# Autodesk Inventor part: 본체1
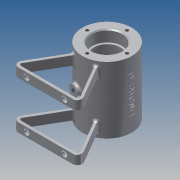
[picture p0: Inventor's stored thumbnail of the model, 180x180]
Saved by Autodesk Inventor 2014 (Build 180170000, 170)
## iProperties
Created: 2016-03
Part Number: 본체1
Material: 알루미늄 6061
Document SubType Name: Modeling
Designer: 406-003
Density: 2.71 g/cm^3
Appearance: 알루미늄 - 평지
Mass: 210.237 g
Surface Area: 325.992 cm^2
Volume: 77.5781 cm^3
Author: 406-003
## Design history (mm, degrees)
sketch "스케치1"
  geometry: C1 r 26 at (0, 0); 1 further point
  constraints: 1 centre point, 1 coincident
  dimensions: "d0" = 52 diameter of C1
extrude "돌출1" new body sketch "스케치1" distance "d1" = 70; taper "d2" = 0 deg
sketch "스케치2"
  geometry: C1 r 26 at (0, 0) reference; 1 further point
  constraints: 1 coincident
hole "구멍1" sketch "스케치2" at (0, 0) diameter "d4" = 28; stored, may be unused: countersink angle "d8" = 90 deg, drill point angle "d10" = 0 deg; dims "d5" = 6, "d6" = 32, "d7" = 12, "d9" = 14
fillet "모깎기1" dims "d11" = 0.3
node "작업 평면1"
sketch "스케치4"
  geometry: L1 (14, -14)-(-14, -14) reference; L2 (14, -56)-(-14, -56) reference; L3 (0, -14)-(0, -56); L4 (21, -14)-(21, -56); L5 (0, -14)-(21, -14); L6 (0, -56)-(21, -56); 1 further point
  constraints: 8 end point, 2 midpoint, 1 parallel, 1 perpendicular, 1 point on line
  dimensions: "d13" = 42 diameter of L4 L3
revolve "회전1" sketch "스케치4" stored, may be unused: angle "d14" = 90 deg
fillet "모깎기2" dims "d15" = 3
fillet "모깎기3" dims "d16" = 0.3
chamfer "모따기1" distance "d17" = 1; stored, may be unused: second distance "d18" = 2, angle "d19" = 45 deg
sketch "스케치5"
  geometry: L1 (0, 21)-(0, -21); C1 r 17 at (0, 0) reference; A1 r 21 centre (0, 0) between (0, 21) and (0, -21)
  constraints: 2 end point, 2 point on circle, 1 centre point, 1 coincident, 1 vertical
  dimensions: "d20" = 42 diameter of A1; "d21" = 0 distance from line of C1.centre L1
hole "구멍2" sketch "스케치5" at (0, 21) diameter "d22" = 3.242; stored, may be unused: countersink angle "d26" = 90 deg, drill point angle "d28" = 118 deg; dims "d23" = 8, "d24" = 32, "d25" = 12, "d27" = 10
node "작업 평면3"
  node "작업 평면2"
sketch "스케치6"
  geometry: L1 (0, 0)-(0, -35); C1 r 5 at (0, -35)
  constraints: 2 end point, 1 centre point, 1 coincident, 1 vertical
  dimensions: "d33" = 35 distance of L1.start L1.end; "d34" = 10 diameter of C1
extrude "돌출2" join sketch "스케치6" stored distance "d35" = 42; taper "d36" = 0 deg
fillet "모깎기4" dims "d37" = 2
sketch "스케치7"
  geometry: C1 r 5 at (0, 0) reference; 2 further points
  constraints: 1 coincident
hole "구멍3" sketch "스케치7" at (0, 0) diameter "d38" = 5.188; stored, may be unused: countersink angle "d42" = 90 deg, drill point angle "d44" = 118 deg; dims "d39" = 19, "d40" = 32, "d41" = 12, "d43" = 20
sketch "스케치8"
  geometry: L1 (0, 0)-(0, -26); L2 (0, 0)-(-7.506, -28.012); C1 r 1.621 at (21, 0) reference; C2 r 1.621 at (0, -21) reference; C3 r 1.621 at (-21, 0) reference; C4 r 1.621 at (0, 21) reference; C5 r 17 at (0, 0) reference; 1 further point
  constraints: 4 end point, 1 vertical, 1 vertical alignment, 1 other
  dimensions: "d46" = 15 deg angle of L2 L1; "d47" = 29 distance of L1.start L2.end
node "작업 평면5"
sketch "스케치9"
  geometry: L1 (0, 0)-(0, -35); C1 r 6 at (0, -35)
  constraints: 2 end point, 1 centre point, 1 coincident, 1 vertical
  dimensions: "d48" = 35 distance of L1.start L1.end; "d49" = 12 diameter of C1
extrude "돌출3" join sketch "스케치9" stored distance "d50" = 42; taper "d51" = 0 deg
sketch "스케치10"
  geometry: C1 r 6 at (0, 0) reference; 2 further points
  constraints: 1 coincident
hole "구멍4" sketch "스케치10" at (0, 0) diameter "d52" = 5.188; stored, may be unused: countersink angle "d56" = 90 deg, drill point angle "d58" = 118 deg; dims "d53" = 19, "d54" = 32, "d55" = 12, "d57" = 20
fillet "모깎기5" dims "d59" = 2
node "작업 평면6"
sketch "스케치11"
  geometry: L1 (0, 0)-(0, -65); L2 (0, -65)-(28.868, -65); L3 (0, -65)-(-28.868, -65); L4 (28.868, -62)-(0, -62); L5 (-28.868, -62)-(0, -62); L6 (-9.499, -22.57)-(-30.598, -58.998); L7 (-11.244, -20)-(-33.182, -57.474); L8 (9.499, -22.57)-(30.598, -58.998); L9 (11.244, -20)-(33.182, -57.474); C1 r 21 at (0, 0) reference; A1 r 5 centre (-28.868, -60) between (-33.182, -57.474) and (-28.868, -65); A2 r 5 centre (28.868, -60) between (28.868, -65) and (33.182, -57.474); A3 r 2 centre (28.868, -60) between (28.868, -62) and (30.598, -58.998); A4 r 2 centre (-28.868, -60) between (-30.598, -58.998) and (-28.868, -62); A5 r 22.944 centre (0, 0) between (-11.244, -20) and (11.244, -20); A6 r 3.457 centre (-28.868, -60) between (-32.011, -61.437) and (-31.687, -62); A7 r 24.487 centre (0, 0) between (-9.499, -22.57) and (9.499, -22.57)
  constraints: 18 end point, 14 point on circle, 7 centre point, 6 tangent, 2 point on line, 1 coincident, 1 collinear, 1 equal radius, 1 perpendicular, 1 vertical, 2 other
  dimensions: "d61" = 65 distance of L1.start L1.end; "d64" = 5 radius of A1; "d65" = 3 distance between parallel lines of L3 L5; "d66" = 3 distance between parallel lines of L2 L4; "d67" = 45 distance from line of L2 L9.start; "d68" = 45 distance from line of L3 L7.start; "d71" = 0.266242 deg angle of L8 L9; "d72" = 59.6539 deg angle of L9 L4; "d73" = 60.4259 deg angle of L6 L9; "d74" = 60.6921 deg angle of L9 L7; "d75" = 30.92281 distance from line of L4.end L9; "d76" = 30.92281 distance from line of L5.end L9; "d79" = 24.4874 radius of A7; "d80" = 22.94403 radius of A5; "d81" = 3.45663 radius of A6
extrude "돌출4" join sketch "스케치11" distance "d82" = 10; taper "d83" = 0 deg
sketch "스케치12"
  geometry: L1 (-33.182, -57.474)-(-12.788, -22.638) reference; L2 (12.788, -22.638)-(33.182, -57.474) reference; L3 (-9.499, -22.57)-(-30.598, -58.998) reference; L4 (9.499, -22.57)-(30.598, -58.998) reference; L5 (28.868, -62)-(0, -62) reference; L6 (-28.868, -62)-(0, -62) reference; A1 r 26 centre (0, 0) between (-12.788, -22.638) and (12.788, -22.638) reference; A2 r 24.487 centre (0, 0) between (-9.499, -22.57) and (9.499, -22.57) reference; A3 r 2 centre (28.868, -60) between (28.868, -62) and (30.598, -58.998) reference; A4 r 2 centre (-28.868, -60) between (-30.598, -58.998) and (-28.868, -62) reference; A5 r 26 centre (0, 0) between (-10.263, -23.889) and (10.263, -23.889); A6 r 26 centre (0, 0) between (12.788, -22.638) and (-12.788, -22.638)
  constraints: 4 point on circle, 2 centre point, 2 end point, 2 point on line, 1 coincident
  dimensions: "d84" = 26 radius of A5
extrude "돌출5" cut sketch "스케치12" distance "d85" = 10; taper "d86" = 0 deg
sketch "스케치13"
  geometry: L1 (0, 0)-(57.735, 0) reference; L2 (57.735, -10)-(0, -10) reference; L3 (28.868, 0)-(28.868, -10); L4 (8.868, 0)-(8.868, -10); L5 (48.868, 0)-(48.868, -10); C1 r 3 at (8.868, -5); C2 r 3 at (48.868, -5); 1 further point
  constraints: 6 end point, 4 midpoint, 2 centre point, 2 parallel
  dimensions: "d87" = 40 distance between parallel lines of L5 L4; "d88" = 20 distance between parallel lines of L3 L4; "d89" = 5 distance from line of L1 C1.centre; "d90" = 6 diameter of C1; "d91" = 6 diameter of C2; "d92" = 5 distance from line of C2.centre L1
extrude "돌출6" cut sketch "스케치13" distance "d93" = 10; taper "d94" = 0 deg
fillet "모깎기6" dims "d95" = 0.5
fillet "모깎기7" dims "d96" = 0.5
fillet "모깎기8" dims "d97" = 3
node "작업 평면8"
node "작업 평면9"
sketch "스케치16"
  geometry: L1 (0, 0)-(0, -35); 1 further point
  constraints: 2 end point, 1 coincident, 1 vertical, 1 other
  dimensions: "d101" = 35 distance of L1.start L1.end
feature "엠보싱2" sketch "스케치16" dims "d0" = 52, "d102" = 0.5, "d103" = 0
node "솔리드1"
mirror "대칭1"
pattern_circular "원형 패턴1" dims angle "d30" = 360 deg
mirror "대칭2"
mirror "대칭3"
mirror "대칭4"
other parameters: "d32" = 3, "d62" = 30 deg, "d63" = 30 deg, "d70" = 22.94403
